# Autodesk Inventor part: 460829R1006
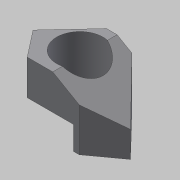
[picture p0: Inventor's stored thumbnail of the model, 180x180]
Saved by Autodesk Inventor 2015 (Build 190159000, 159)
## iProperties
Created: 2016-08
Part Number: 460829R1006
Material: 일반
Document SubType Name: Modeling
Designer: jio
Density: 1 g/cm^3
Appearance: 기본값
Author: jio
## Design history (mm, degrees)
sketch "스케치1"
  geometry: 1 further point
sketch "스케치2"
  geometry: L1 (-9.387, 55)-(34, 55); L2 (34, 55)-(104.673, -18.184); L3 (104.673, -18.184)-(54, -55); L4 (54, -55)-(-34.842, -55); L5 (-34.842, -55)-(-70, -10); L6 (-70, -10)-(-9.387, 55); C1 r 39.5 at (0, 0); 1 further point
  constraints: 12 end point, 1 centre point, 1 coincident, 1 horizontal, 1 parallel
  dimensions: "d0" = 79 diameter of C1; "d1" = 124 horizontal distance of L3.end L5.end; "d2" = 104 horizontal distance of L5.end L1.end; "d3" = 110 distance between parallel lines of L4 L1; "d4" = 134 deg angle of L2 L1; "d5" = 144 deg angle of L3 L4; "d6" = 128 deg angle of L4 L5; "d7" = 99 deg angle of L5 L6; "d8" = 45 vertical distance of L4.end L5.end; "d9" = 70 horizontal distance of L5.end point (0, 0); "d10" = 55 vertical distance of L3.end point (0, 0)
extrude "돌출1" new body sketch "스케치2" distance "d11" = 100; taper "d12" = 0 deg
sketch "스케치3"
  geometry: L1 (-70, 15)-(44, 15); L2 (44, 15)-(44, -55); L3 (44, -55)-(-70, -55); L4 (-70, -55)-(-70, 15); L5 (-34.842, -55)-(54, -55) reference; 2 further points
  constraints: 8 end point, 2 parallel, 1 collinear, 1 horizontal, 1 perpendicular, 1 point on line
  dimensions: "d13" = 114 distance of L2.end L3.end; "d14" = 70 distance of L1.end L2.end
extrude "돌출2" cut sketch "스케치3" distance "d15" = 40; taper "d16" = 0 deg
sketch "스케치4"
  geometry: L1 (88.842, -100)-(88.842, 0) reference; L2 (0, 0)-(88.842, 0) reference; L3 (43.515, 0)-(139.515, 0); L4 (139.515, 0)-(139.515, -55.426); L5 (139.515, -55.426)-(43.515, 0); L6 (139.515, -100)-(139.515, 0) reference; 1 further point
  constraints: 6 end point, 1 collinear, 1 horizontal, 1 parallel, 1 point on line
  dimensions: "d17" = 96 distance of L3.start L3.end; "d18" = 30 deg angle of L5 L2
extrude "돌출3" cut sketch "스케치4" stored distance "d19" = 40; taper "d20" = 0 deg
node "솔리드1"
